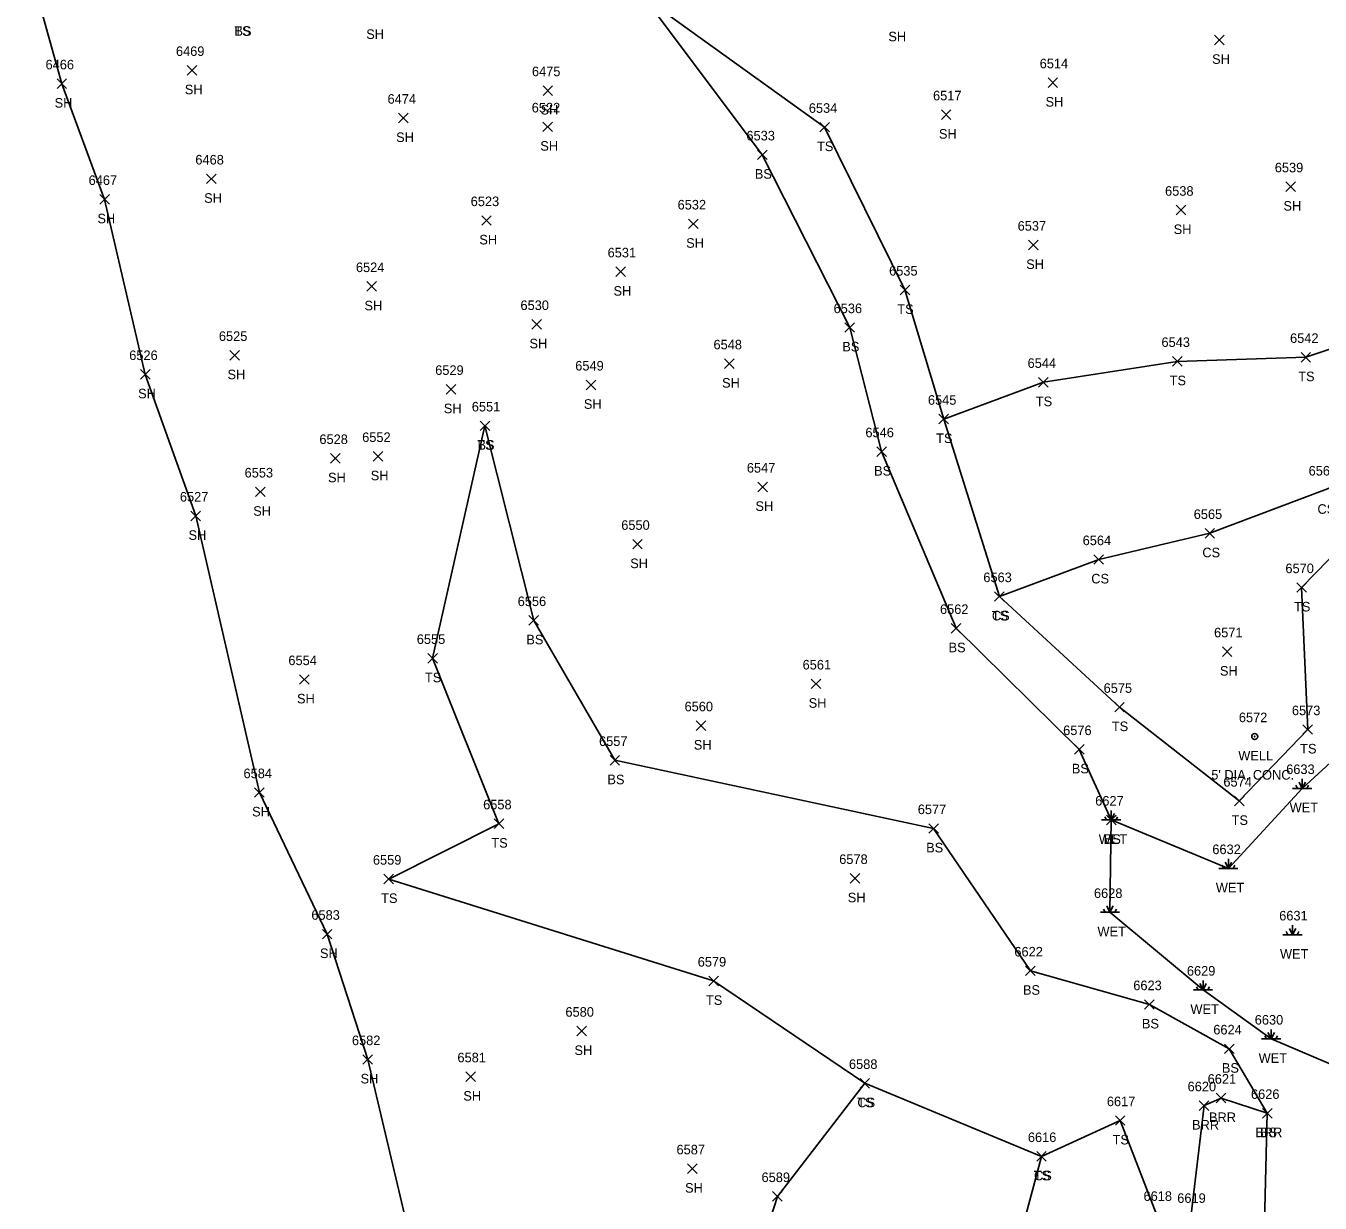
# Model space of a CAD drawing. Extents: x 1472233 to 1475777, y 540726 to 543442.
# Drawn here: x 1472282.2 to 1472552.6, y 541249 to 541495 of the extents above; entities that cross this region are included whole.
import ezdxf

# ---------------------------------------------------------------- set-up
doc = ezdxf.new("R2010")
doc.units = 0
for name, color, linetype in [('L_A', 7, 'Continuous'), ('L_I', 7, 'Continuous'), ('L_TIC', 7, 'Continuous'), ('LABL', 7, 'Continuous'), ('LELB', 7, 'Continuous'), ('LSOGP', 7, 'Continuous'), ('LWET', 7, 'Continuous'), ('U_A', 7, 'Continuous'), ('U_C', 7, 'Continuous'), ('U_I', 7, 'Continuous'), ('UWW', 7, 'Continuous')]:
    doc.layers.add(name, color=color, linetype=linetype)

msp = doc.modelspace()

# ---------------------------------------------------------------- linework, layer by layer
at = {"layer": 'L_TIC'}
for points in [[(1472530.58, 541491.04), (1472532.58, 541493.04)], [(1472532.58, 541491.04), (1472530.58, 541493.04)], [(1472315.88, 541484.69), (1472317.88, 541486.69)], [(1472317.88, 541484.69), (1472315.88, 541486.69)], [(1472288.68, 541481.89), (1472290.68, 541483.89)], [(1472290.68, 541481.89), (1472288.68, 541483.89)], [(1472495.77, 541482.11), (1472497.77, 541484.11)], [(1472497.77, 541482.11), (1472495.77, 541484.11)], [(1472390.23, 541480.46), (1472392.23, 541482.46)], [(1472392.23, 541480.46), (1472390.23, 541482.46)], [(1472360.04, 541474.71), (1472362.04, 541476.71)], [(1472362.04, 541474.71), (1472360.04, 541476.71)], [(1472390.18, 541472.89), (1472392.18, 541474.89)], [(1472392.18, 541472.89), (1472390.18, 541474.89)], [(1472448.08, 541472.81), (1472450.08, 541474.81)], [(1472450.08, 541472.81), (1472448.08, 541474.81)], [(1472473.48, 541475.41), (1472475.48, 541477.41)], [(1472475.48, 541475.41), (1472473.48, 541477.41)], [(1472435.05, 541467.04), (1472437.05, 541469.04)], [(1472437.05, 541467.04), (1472435.05, 541469.04)], [(1472319.93, 541462.01), (1472321.93, 541464.01)], [(1472321.93, 541462.01), (1472319.93, 541464.01)], [(1472545.48, 541460.37), (1472547.48, 541462.37)], [(1472547.48, 541460.37), (1472545.48, 541462.37)], [(1472297.62, 541457.73), (1472299.62, 541459.73)], [(1472299.62, 541457.73), (1472297.62, 541459.73)], [(1472522.54, 541455.48), (1472524.54, 541457.48)], [(1472524.54, 541455.48), (1472522.54, 541457.48)], [(1472377.43, 541453.31), (1472379.43, 541455.31)], [(1472379.43, 541453.31), (1472377.43, 541455.31)], [(1472420.66, 541452.61), (1472422.66, 541454.61)], [(1472422.66, 541452.61), (1472420.66, 541454.61)], [(1472491.72, 541448.18), (1472493.72, 541450.18)], [(1472493.72, 541448.18), (1472491.72, 541450.18)], [(1472405.47, 541442.6), (1472407.47, 541444.6)], [(1472407.47, 541442.6), (1472405.47, 541444.6)], [(1472353.43, 541439.53), (1472355.43, 541441.53)], [(1472355.43, 541439.53), (1472353.43, 541441.53)], [(1472464.86, 541438.79), (1472466.86, 541440.79)], [(1472466.86, 541438.79), (1472464.86, 541440.79)], [(1472387.91, 541431.6), (1472389.91, 541433.6)], [(1472389.91, 541431.6), (1472387.91, 541433.6)], [(1472453.32, 541430.95), (1472455.32, 541432.95)], [(1472455.32, 541430.95), (1472453.32, 541432.95)], [(1472324.8, 541425.14), (1472326.8, 541427.14)], [(1472326.8, 541425.14), (1472324.8, 541427.14)], [(1472548.65, 541424.73), (1472550.65, 541426.73)], [(1472550.65, 541424.73), (1472548.65, 541426.73)], [(1472428.17, 541423.38), (1472430.17, 541425.38)], [(1472430.17, 541423.38), (1472428.17, 541425.38)], [(1472521.78, 541423.88), (1472523.78, 541425.88)], [(1472523.78, 541423.88), (1472521.78, 541425.88)], [(1472306.12, 541421.15), (1472308.12, 541423.15)], [(1472308.12, 541421.15), (1472306.12, 541423.15)], [(1472399.28, 541418.96), (1472401.28, 541420.96)], [(1472401.28, 541418.96), (1472399.28, 541420.96)], [(1472493.81, 541419.51), (1472495.81, 541421.51)], [(1472495.81, 541419.51), (1472493.81, 541421.51)], [(1472370.01, 541418.04), (1472372.01, 541420.04)], [(1472372.01, 541418.04), (1472370.01, 541420.04)], [(1472472.98, 541411.81), (1472474.98, 541413.81)], [(1472474.98, 541411.81), (1472472.98, 541413.81)], [(1472472.98, 541411.81), (1472474.98, 541413.81)], [(1472474.98, 541411.81), (1472472.98, 541413.81)], [(1472377.09, 541410.41), (1472379.09, 541412.41)], [(1472379.09, 541410.41), (1472377.09, 541412.41)], [(1472377.09, 541410.41), (1472379.09, 541412.41)], [(1472379.09, 541410.41), (1472377.09, 541412.41)], [(1472345.81, 541403.6), (1472347.81, 541405.6)], [(1472347.81, 541403.6), (1472345.81, 541405.6)], [(1472354.75, 541404.02), (1472356.75, 541406.02)], [(1472356.75, 541404.02), (1472354.75, 541406.02)], [(1472459.98, 541405.01), (1472461.98, 541407.01)], [(1472461.98, 541405.01), (1472459.98, 541407.01)], [(1472435.14, 541397.63), (1472437.14, 541399.63)], [(1472437.14, 541397.63), (1472435.14, 541399.63)], [(1472330.18, 541396.61), (1472332.18, 541398.61)], [(1472332.18, 541396.61), (1472330.18, 541398.61)], [(1472316.66, 541391.58), (1472318.66, 541393.58)], [(1472318.66, 541391.58), (1472316.66, 541393.58)], [(1472528.58, 541387.94), (1472530.58, 541389.94)], [(1472530.58, 541387.94), (1472528.58, 541389.94)], [(1472408.97, 541385.67), (1472410.97, 541387.67)], [(1472410.97, 541385.67), (1472408.97, 541387.67)], [(1472505.37, 541382.47), (1472507.37, 541384.47)], [(1472507.37, 541382.47), (1472505.37, 541384.47)], [(1472547.77, 541376.62), (1472549.77, 541378.62)], [(1472549.77, 541376.62), (1472547.77, 541378.62)], [(1472484.6, 541374.74), (1472486.6, 541376.74)], [(1472486.6, 541374.74), (1472484.6, 541376.74)], [(1472484.6, 541374.74), (1472486.6, 541376.74)], [(1472486.6, 541374.74), (1472484.6, 541376.74)], [(1472387.3, 541369.74), (1472389.3, 541371.74)], [(1472389.3, 541369.74), (1472387.3, 541371.74)], [(1472475.54, 541368.09), (1472477.54, 541370.09)], [(1472477.54, 541368.09), (1472475.54, 541370.09)], [(1472532.21, 541363.21), (1472534.21, 541365.21)], [(1472534.21, 541363.21), (1472532.21, 541365.21)], [(1472366.15, 541361.82), (1472368.15, 541363.82)], [(1472368.15, 541361.82), (1472366.15, 541363.82)], [(1472339.33, 541357.4), (1472341.33, 541359.4)], [(1472341.33, 541357.4), (1472339.33, 541359.4)], [(1472446.26, 541356.49), (1472448.26, 541358.49)], [(1472448.26, 541356.49), (1472446.26, 541358.49)], [(1472509.7, 541351.61), (1472511.7, 541353.61)], [(1472511.7, 541351.61), (1472509.7, 541353.61)], [(1472509.7, 541351.61), (1472511.7, 541353.61)], [(1472511.7, 541351.61), (1472509.7, 541353.61)], [(1472422.25, 541347.75), (1472424.25, 541349.75)], [(1472424.25, 541347.75), (1472422.25, 541349.75)], [(1472549.05, 541346.94), (1472551.05, 541348.94)], [(1472551.05, 541346.94), (1472549.05, 541348.94)], [(1472404.25, 541340.51), (1472406.25, 541342.51)], [(1472406.25, 541340.51), (1472404.25, 541342.51)], [(1472501.3, 541342.78), (1472503.3, 541344.78)], [(1472503.3, 541342.78), (1472501.3, 541344.78)], [(1472329.95, 541333.78), (1472331.95, 541335.78)], [(1472331.95, 541333.78), (1472329.95, 541335.78)], [(1472534.73, 541332.01), (1472536.73, 541334.01)], [(1472536.73, 541332.01), (1472534.73, 541334.01)], [(1472380.02, 541327.26), (1472382.02, 541329.26)], [(1472382.02, 541327.26), (1472380.02, 541329.26)], [(1472507.98, 541328.05), (1472509.98, 541330.05)], [(1472509.98, 541328.05), (1472507.98, 541330.05)], [(1472470.86, 541326.27), (1472472.86, 541328.27)], [(1472472.86, 541326.27), (1472470.86, 541328.27)], [(1472356.99, 541315.7), (1472358.99, 541317.7)], [(1472358.99, 541315.7), (1472356.99, 541317.7)], [(1472454.43, 541315.84), (1472456.43, 541317.84)], [(1472456.43, 541315.84), (1472454.43, 541317.84)], [(1472344.13, 541304.19), (1472346.13, 541306.19)], [(1472346.13, 541304.19), (1472344.13, 541306.19)], [(1472424.88, 541294.4), (1472426.88, 541296.4)], [(1472426.88, 541294.4), (1472424.88, 541296.4)], [(1472491.09, 541296.52), (1472493.09, 541298.52)], [(1472493.09, 541296.52), (1472491.09, 541298.52)], [(1472515.95, 541289.48), (1472517.95, 541291.48)], [(1472517.95, 541289.48), (1472515.95, 541291.48)], [(1472397.32, 541283.93), (1472399.32, 541285.93)], [(1472399.32, 541283.93), (1472397.32, 541285.93)], [(1472532.66, 541280.23), (1472534.66, 541282.23)], [(1472534.66, 541280.23), (1472532.66, 541282.23)], [(1472352.61, 541277.99), (1472354.61, 541279.99)], [(1472354.61, 541277.99), (1472352.61, 541279.99)], [(1472374.09, 541274.4), (1472376.09, 541276.4)], [(1472376.09, 541274.4), (1472374.09, 541276.4)], [(1472456.48, 541273.02), (1472458.48, 541275.02)], [(1472458.48, 541273.02), (1472456.48, 541275.02)], [(1472456.48, 541273.02), (1472458.48, 541275.02)], [(1472458.48, 541273.02), (1472456.48, 541275.02)], [(1472530.92, 541269.93), (1472532.92, 541271.93)], [(1472532.92, 541269.93), (1472530.92, 541271.93)], [(1472527.38, 541268.35), (1472529.38, 541270.35)], [(1472529.38, 541268.35), (1472527.38, 541270.35)], [(1472509.85, 541265.24), (1472511.85, 541267.24)], [(1472511.85, 541265.24), (1472509.85, 541267.24)], [(1472540.6, 541266.76), (1472542.6, 541268.76)], [(1472542.6, 541266.76), (1472540.6, 541268.76)], [(1472540.6, 541266.76), (1472542.6, 541268.76)], [(1472542.6, 541266.76), (1472540.6, 541268.76)], [(1472493.4, 541257.74), (1472495.4, 541259.74)], [(1472495.4, 541257.74), (1472493.4, 541259.74)], [(1472493.4, 541257.74), (1472495.4, 541259.74)], [(1472495.4, 541257.74), (1472493.4, 541259.74)], [(1472420.43, 541255.17), (1472422.43, 541257.17)], [(1472422.43, 541255.17), (1472420.43, 541257.17)], [(1472438.21, 541249.38), (1472440.21, 541251.38)], [(1472440.21, 541249.38), (1472438.21, 541251.38)]]:
    msp.add_lwpolyline(points, dxfattribs=at)
at = {"layer": 'LABL'}
msp.add_lwpolyline([(1472469.15, 541041.01), (1472475.97, 541055.47), (1472488.36, 541118.51), (1472504.97, 541170), (1472510.71, 541208.46), (1472518.52, 541246.45), (1472525.58, 541246.03), (1472528.38, 541269.35), (1472531.92, 541270.93), (1472541.6, 541267.76), (1472540.85, 541239.24), (1472542.19, 541207.56), (1472538.9, 541194.52), (1472527.34, 541167.71), (1472526.09, 541134.29), (1472517.05, 541115.78), (1472517.21, 541096.13), (1472506.36, 541063.94), (1472508.35, 541054.85), (1472520.49, 541023.91), (1472524.8, 541007.77), (1472520.6, 540985.68), (1472515.09, 540974.04), (1472487.1, 540968.56)], dxfattribs=at)
at = {"layer": 'LELB'}
for points in [[(1472411.41, 541500.89), (1472449.08, 541473.81), (1472465.86, 541439.79), (1472473.98, 541412.81), (1472485.6, 541375.74), (1472510.7, 541352.61)], [(1472411.41, 541500.89), (1472436.05, 541468.04), (1472454.32, 541431.95), (1472460.98, 541406.01), (1472476.54, 541369.09), (1472502.3, 541343.78), (1472508.98, 541329.05)], [(1472574.97, 541434.22), (1472549.65, 541425.73), (1472522.78, 541424.88), (1472494.81, 541420.51), (1472473.98, 541412.81)], [(1472378.09, 541411.41), (1472367.15, 541362.82), (1472381.02, 541328.26), (1472357.99, 541316.7), (1472425.88, 541295.4), (1472457.48, 541274.02), (1472494.4, 541258.74), (1472510.85, 541266.24), (1472518.52, 541246.45)], [(1472378.09, 541411.41), (1472388.3, 541370.74), (1472405.25, 541341.51), (1472471.86, 541327.27), (1472492.09, 541297.52), (1472516.95, 541290.48), (1472533.66, 541281.23), (1472541.6, 541267.76)], [(1472485.6, 541375.74), (1472506.37, 541383.47), (1472529.58, 541388.94), (1472553.64, 541398.02), (1472580.58, 541408.64)], [(1472585.1, 541401.08), (1472565.75, 541395.05), (1472548.77, 541377.62), (1472550.05, 541347.94), (1472535.73, 541333.01), (1472510.7, 541352.61)], [(1472457.48, 541274.02), (1472439.21, 541250.38), (1472430.56, 541223.51), (1472414.79, 541203.44), (1472398.94, 541187.62), (1472409.66, 541165.62), (1472437.48, 541161.44), (1472451.76, 541163.36), (1472465.61, 541194.99), (1472486.49, 541228.95), (1472494.4, 541258.74)]]:
    msp.add_lwpolyline(points, dxfattribs=at)
at = {"layer": 'LSOGP'}
msp.add_lwpolyline([(1472364.96, 541231.03), (1472353.61, 541278.99), (1472345.13, 541305.19), (1472330.95, 541334.78), (1472317.66, 541392.58), (1472307.12, 541422.15), (1472298.62, 541458.73), (1472289.68, 541482.89), (1472282.16, 541509.86)], dxfattribs=at)
at = {"layer": 'LWET'}
for p, q in [((1472548.89, 541335.64), (1472548.23, 541336.97)), ((1472548.89, 541335.64), (1472548.89, 541337.64)), ((1472548.89, 541335.64), (1472549.56, 541336.97)), ((1472550.89, 541335.64), (1472546.89, 541335.64)), ((1472547.89, 541335.64), (1472547.56, 541336.31)), ((1472549.89, 541335.64), (1472550.23, 541336.31)), ((1472510.98, 541329.05), (1472506.98, 541329.05)), ((1472510.98, 541329.05), (1472506.98, 541329.05)), ((1472507.98, 541329.05), (1472507.65, 541329.72)), ((1472507.98, 541329.05), (1472507.65, 541329.72)), ((1472508.98, 541329.05), (1472508.32, 541330.39)), ((1472508.98, 541329.05), (1472508.32, 541330.39)), ((1472508.98, 541329.05), (1472508.98, 541331.05)), ((1472508.98, 541329.05), (1472508.98, 541331.05)), ((1472508.98, 541329.05), (1472509.65, 541330.39)), ((1472508.98, 541329.05), (1472509.65, 541330.39)), ((1472509.98, 541329.05), (1472510.32, 541329.72)), ((1472509.98, 541329.05), (1472510.32, 541329.72)), ((1472533.47, 541318.91), (1472533.47, 541320.91)), ((1472535.47, 541318.91), (1472531.47, 541318.91)), ((1472532.47, 541318.91), (1472532.13, 541319.57)), ((1472533.47, 541318.91), (1472532.8, 541320.24)), ((1472533.47, 541318.91), (1472534.13, 541320.24)), ((1472534.47, 541318.91), (1472534.8, 541319.57)), ((1472507.72, 541309.75), (1472507.39, 541310.42)), ((1472508.72, 541309.75), (1472508.05, 541311.08)), ((1472508.72, 541309.75), (1472508.72, 541311.75)), ((1472508.72, 541309.75), (1472509.39, 541311.08)), ((1472509.72, 541309.75), (1472510.05, 541310.42)), ((1472510.72, 541309.75), (1472506.72, 541309.75)), ((1472548.87, 541305.05), (1472544.87, 541305.05)), ((1472545.87, 541305.05), (1472545.54, 541305.72)), ((1472546.87, 541305.05), (1472546.2, 541306.39)), ((1472546.87, 541305.05), (1472546.87, 541307.05)), ((1472546.87, 541305.05), (1472547.54, 541306.39)), ((1472547.87, 541305.05), (1472548.2, 541305.72)), ((1472527.16, 541293.52), (1472526.82, 541294.19)), ((1472528.16, 541293.52), (1472527.49, 541294.86)), ((1472528.16, 541293.52), (1472528.16, 541295.52)), ((1472528.16, 541293.52), (1472528.82, 541294.86)), ((1472529.16, 541293.52), (1472529.49, 541294.19)), ((1472530.16, 541293.52), (1472526.16, 541293.52)), ((1472544.41, 541283.29), (1472540.41, 541283.29)), ((1472541.41, 541283.29), (1472541.07, 541283.96)), ((1472542.41, 541283.29), (1472541.74, 541284.62)), ((1472542.41, 541283.29), (1472542.41, 541285.29)), ((1472542.41, 541283.29), (1472543.07, 541284.62)), ((1472543.41, 541283.29), (1472543.74, 541283.96))]:
    msp.add_line(p, q, dxfattribs=at)
for points in [[(1472508.98, 541329.05), (1472533.47, 541318.91), (1472548.89, 541335.64), (1472559.01, 541344.89), (1472577.68, 541343.07), (1472594.03, 541341.67), (1472610.83, 541345.33), (1472629.56, 541348.93), (1472628.53, 541342.62), (1472631.4, 541337.21), (1472633.46, 541334.15)], [(1472508.98, 541329.05), (1472508.72, 541309.75), (1472528.16, 541293.52), (1472542.41, 541283.29), (1472556.84, 541277.18), (1472573.73, 541267.28), (1472596.68, 541254.85)]]:
    msp.add_lwpolyline(points, dxfattribs=at)
at = {"layer": 'UWW'}
for radius in [0.625, 0.0833]:
    msp.add_circle((1472538.96, 541346.48), radius, dxfattribs=at)

# ---------------------------------------------------------------- texts
at = {"layer": 'L_A'}
for s, p in [('TS', (1472325.7, 541492.9)), ('BS', (1472325.74, 541492.9)), ('SH', (1472353.29, 541492.25)), ('SH', (1472462.4, 541491.75)), ('SH', (1472530.06, 541487.04)), ('SH', (1472315.37, 541480.69)), ('SH', (1472288.16, 541477.89)), ('SH', (1472389.72, 541476.46)), ('SH', (1472495.25, 541478.11)), ('SH', (1472359.53, 541470.71)), ('SH', (1472472.97, 541471.41)), ('SH', (1472389.67, 541468.89)), ('TS', (1472447.49, 541468.81)), ('BS', (1472434.49, 541463.04)), ('SH', (1472319.42, 541458.01)), ('SH', (1472544.97, 541456.37)), ('SH', (1472297.11, 541453.73)), ('SH', (1472522.03, 541451.48)), ('SH', (1472376.92, 541449.31)), ('SH', (1472420.15, 541448.61)), ('SH', (1472491.21, 541444.18)), ('SH', (1472404.96, 541438.6)), ('SH', (1472352.92, 541435.53)), ('TS', (1472464.27, 541434.79)), ('SH', (1472387.4, 541427.6)), ('BS', (1472452.77, 541426.95)), ('SH', (1472324.29, 541421.14)), ('SH', (1472427.65, 541419.38)), ('TS', (1472521.19, 541419.88)), ('TS', (1472548.06, 541420.73)), ('SH', (1472305.61, 541417.15)), ('SH', (1472369.5, 541414.04)), ('SH', (1472398.77, 541414.96)), ('TS', (1472493.22, 541415.51)), ('TS', (1472376.5, 541406.41)), ('BS', (1472376.53, 541406.41)), ('TS', (1472472.39, 541407.81)), ('TS', (1472472.39, 541407.81)), ('SH', (1472354.23, 541400.02)), ('BS', (1472459.42, 541401.01)), ('SH', (1472345.3, 541399.6)), ('SH', (1472329.67, 541392.61)), ('SH', (1472434.63, 541393.63)), ('CS', (1472552.08, 541393.02)), ('SH', (1472316.15, 541387.58)), ('CS', (1472528.02, 541383.94)), ('SH', (1472408.46, 541381.67)), ('CS', (1472504.81, 541378.47)), ('TS', (1472484.01, 541370.74)), ('CS', (1472484.04, 541370.74)), ('TS', (1472547.18, 541372.62)), ('BS', (1472386.74, 541365.74)), ('BS', (1472474.98, 541364.09)), ('SH', (1472531.7, 541359.21)), ('TS', (1472365.56, 541357.82)), ('SH', (1472338.82, 541353.4)), ('SH', (1472445.75, 541352.49)), ('TS', (1472509.11, 541347.61)), ('TS', (1472509.11, 541347.61)), ('SH', (1472421.74, 541343.75)), ('TS', (1472548.46, 541342.94)), ('BS', (1472500.74, 541338.78)), ('BS', (1472403.69, 541336.51)), ('SH', (1472329.44, 541329.78)), ('WET', (1472546.27, 541330.64)), ('TS', (1472534.14, 541328.01)), ('WET', (1472506.36, 541324.05)), ('WET', (1472506.36, 541324.05)), ('BS', (1472507.42, 541324.05)), ('TS', (1472379.43, 541323.26)), ('BS', (1472470.3, 541322.27)), ('WET', (1472530.84, 541313.91)), ('TS', (1472356.4, 541311.7)), ('SH', (1472453.92, 541311.84)), ('WET', (1472506.1, 541304.75)), ('SH', (1472343.61, 541300.19)), ('WET', (1472544.25, 541300.05)), ('BS', (1472490.53, 541292.52)), ('TS', (1472424.29, 541290.4)), ('WET', (1472525.53, 541288.52)), ('BS', (1472515.39, 541285.48)), ('SH', (1472396.8, 541279.93)), ('WET', (1472539.79, 541278.29)), ('BS', (1472532.1, 541276.23)), ('SH', (1472352.1, 541273.99)), ('SH', (1472373.58, 541270.4)), ('TS', (1472455.89, 541269.02)), ('CS', (1472455.92, 541269.02)), ('BRR', (1472529.4, 541265.93)), ('BRR', (1472525.87, 541264.35)), ('BRR', (1472539.09, 541262.76)), ('BS', (1472540.04, 541262.76)), ('TS', (1472509.26, 541261.24)), ('TS', (1472492.81, 541253.74)), ('CS', (1472492.84, 541253.74)), ('SH', (1472419.92, 541251.17))]:
    msp.add_text(s, height=2, dxfattribs=at).set_placement(p)
at = {"layer": 'L_I'}
for s, p in [('6469', (1472313.52, 541488.69)), ('6466', (1472286.27, 541485.89)), ('6475', (1472387.92, 541484.46)), ('6514', (1472494.03, 541486.11)), ('6474', (1472357.74, 541478.71)), ('6517', (1472471.74, 541479.41)), ('6522', (1472387.87, 541476.89)), ('6534', (1472445.78, 541476.81)), ('6533', (1472432.74, 541471.04)), ('6468', (1472317.58, 541466.01)), ('6539', (1472543.16, 541464.37)), ('6467', (1472295.27, 541461.73)), ('6538', (1472520.23, 541459.48)), ('6523', (1472375.12, 541457.31)), ('6532', (1472418.36, 541456.61)), ('6537', (1472489.42, 541452.18)), ('6531', (1472403.73, 541446.6)), ('6524', (1472351.13, 541443.53)), ('6535', (1472462.56, 541442.79)), ('6530', (1472385.52, 541435.6)), ('6536', (1472450.96, 541434.95)), ('6525', (1472322.49, 541429.14)), ('6548', (1472425.86, 541427.38)), ('6543', (1472519.48, 541427.88)), ('6542', (1472546.35, 541428.73)), ('6526', (1472303.76, 541425.15)), ('6529', (1472367.7, 541422.04)), ('6549', (1472396.97, 541422.96)), ('6544', (1472491.5, 541423.51)), ('6551', (1472375.35, 541414.41)), ('6551', (1472375.35, 541414.41)), ('6545', (1472470.67, 541415.81)), ('6545', (1472470.67, 541415.81)), ('6552', (1472352.44, 541408.02)), ('6546', (1472457.61, 541409.01)), ('6528', (1472343.5, 541407.6)), ('6553', (1472327.87, 541400.61)), ('6547', (1472432.83, 541401.63)), ('6566', (1472550.23, 541401.02)), ('6527', (1472314.35, 541395.58)), ('6565', (1472526.22, 541391.94)), ('6550', (1472406.58, 541389.67)), ('6564', (1472503.01, 541386.47)), ('6563', (1472482.25, 541378.74)), ('6563', (1472482.25, 541378.74)), ('6570', (1472545.38, 541380.62)), ('6556', (1472384.94, 541373.74)), ('6562', (1472473.19, 541372.09)), ('6555', (1472363.85, 541365.82)), ('6571', (1472530.47, 541367.21)), ('6554', (1472337.02, 541361.4)), ('6561', (1472444.48, 541360.49)), ('6575', (1472507.39, 541355.61)), ('6575', (1472507.39, 541355.61)), ('6560', (1472419.81, 541351.75)), ('6573', (1472546.74, 541350.94)), ('6576', (1472498.93, 541346.78)), ('6557', (1472401.94, 541344.51)), ('6584', (1472327.64, 541337.78)), ('6633', (1472545.54, 541338.64)), ('6574', (1472532.42, 541336.01)), ('6558', (1472377.72, 541331.26)), ('6577', (1472468.55, 541330.27)), ('6627', (1472505.63, 541332.05)), ('6627', (1472505.63, 541332.05)), ('6627', (1472505.63, 541332.05)), ('6632', (1472530.11, 541321.91)), ('6559', (1472354.68, 541319.7)), ('6578', (1472452.13, 541319.84)), ('6628', (1472505.37, 541312.75)), ('6583', (1472341.82, 541308.19)), ('6631', (1472544.08, 541308.05)), ('6622', (1472488.74, 541300.52)), ('6579', (1472422.56, 541298.4)), ('6629', (1472524.79, 541296.52)), ('6623', (1472513.59, 541293.48)), ('6580', (1472394.92, 541287.93)), ('6630', (1472538.97, 541286.29)), ('6624', (1472530.31, 541284.23)), ('6582', (1472350.3, 541281.99)), ('6581', (1472372.35, 541278.4)), ('6588', (1472454.17, 541277.02)), ('6588', (1472454.17, 541277.02)), ('6621', (1472529.13, 541273.93)), ('6620', (1472524.94, 541272.35)), ('6626', (1472538.19, 541270.76)), ('6626', (1472538.19, 541270.76)), ('6617', (1472508.07, 541269.24)), ('6587', (1472418.13, 541259.17)), ('6616', (1472491.56, 541261.74)), ('6616', (1472491.56, 541261.74)), ('6589', (1472435.9, 541253.38)), ('6618', (1472515.73, 541249.45)), ('6618', (1472515.73, 541249.45)), ('6619', (1472522.78, 541249.03)), ('6619', (1472522.78, 541249.03))]:
    msp.add_text(s, height=2, dxfattribs=at).set_placement(p)
at = {"layer": 'U_A'}
msp.add_text('WELL', height=2, dxfattribs=at).set_placement((1472535.53, 541341.48))
at = {"layer": 'U_C'}
msp.add_text("5' DIA. CONC.", height=2, dxfattribs=at).set_placement((1472529.89, 541337.48))
at = {"layer": 'U_I'}
msp.add_text('6572', height=2, dxfattribs=at).set_placement((1472535.65, 541349.48))

doc.saveas('drawing.dxf')
